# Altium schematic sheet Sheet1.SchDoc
size A3; SheetNumber: 1; SheetTotal: 1
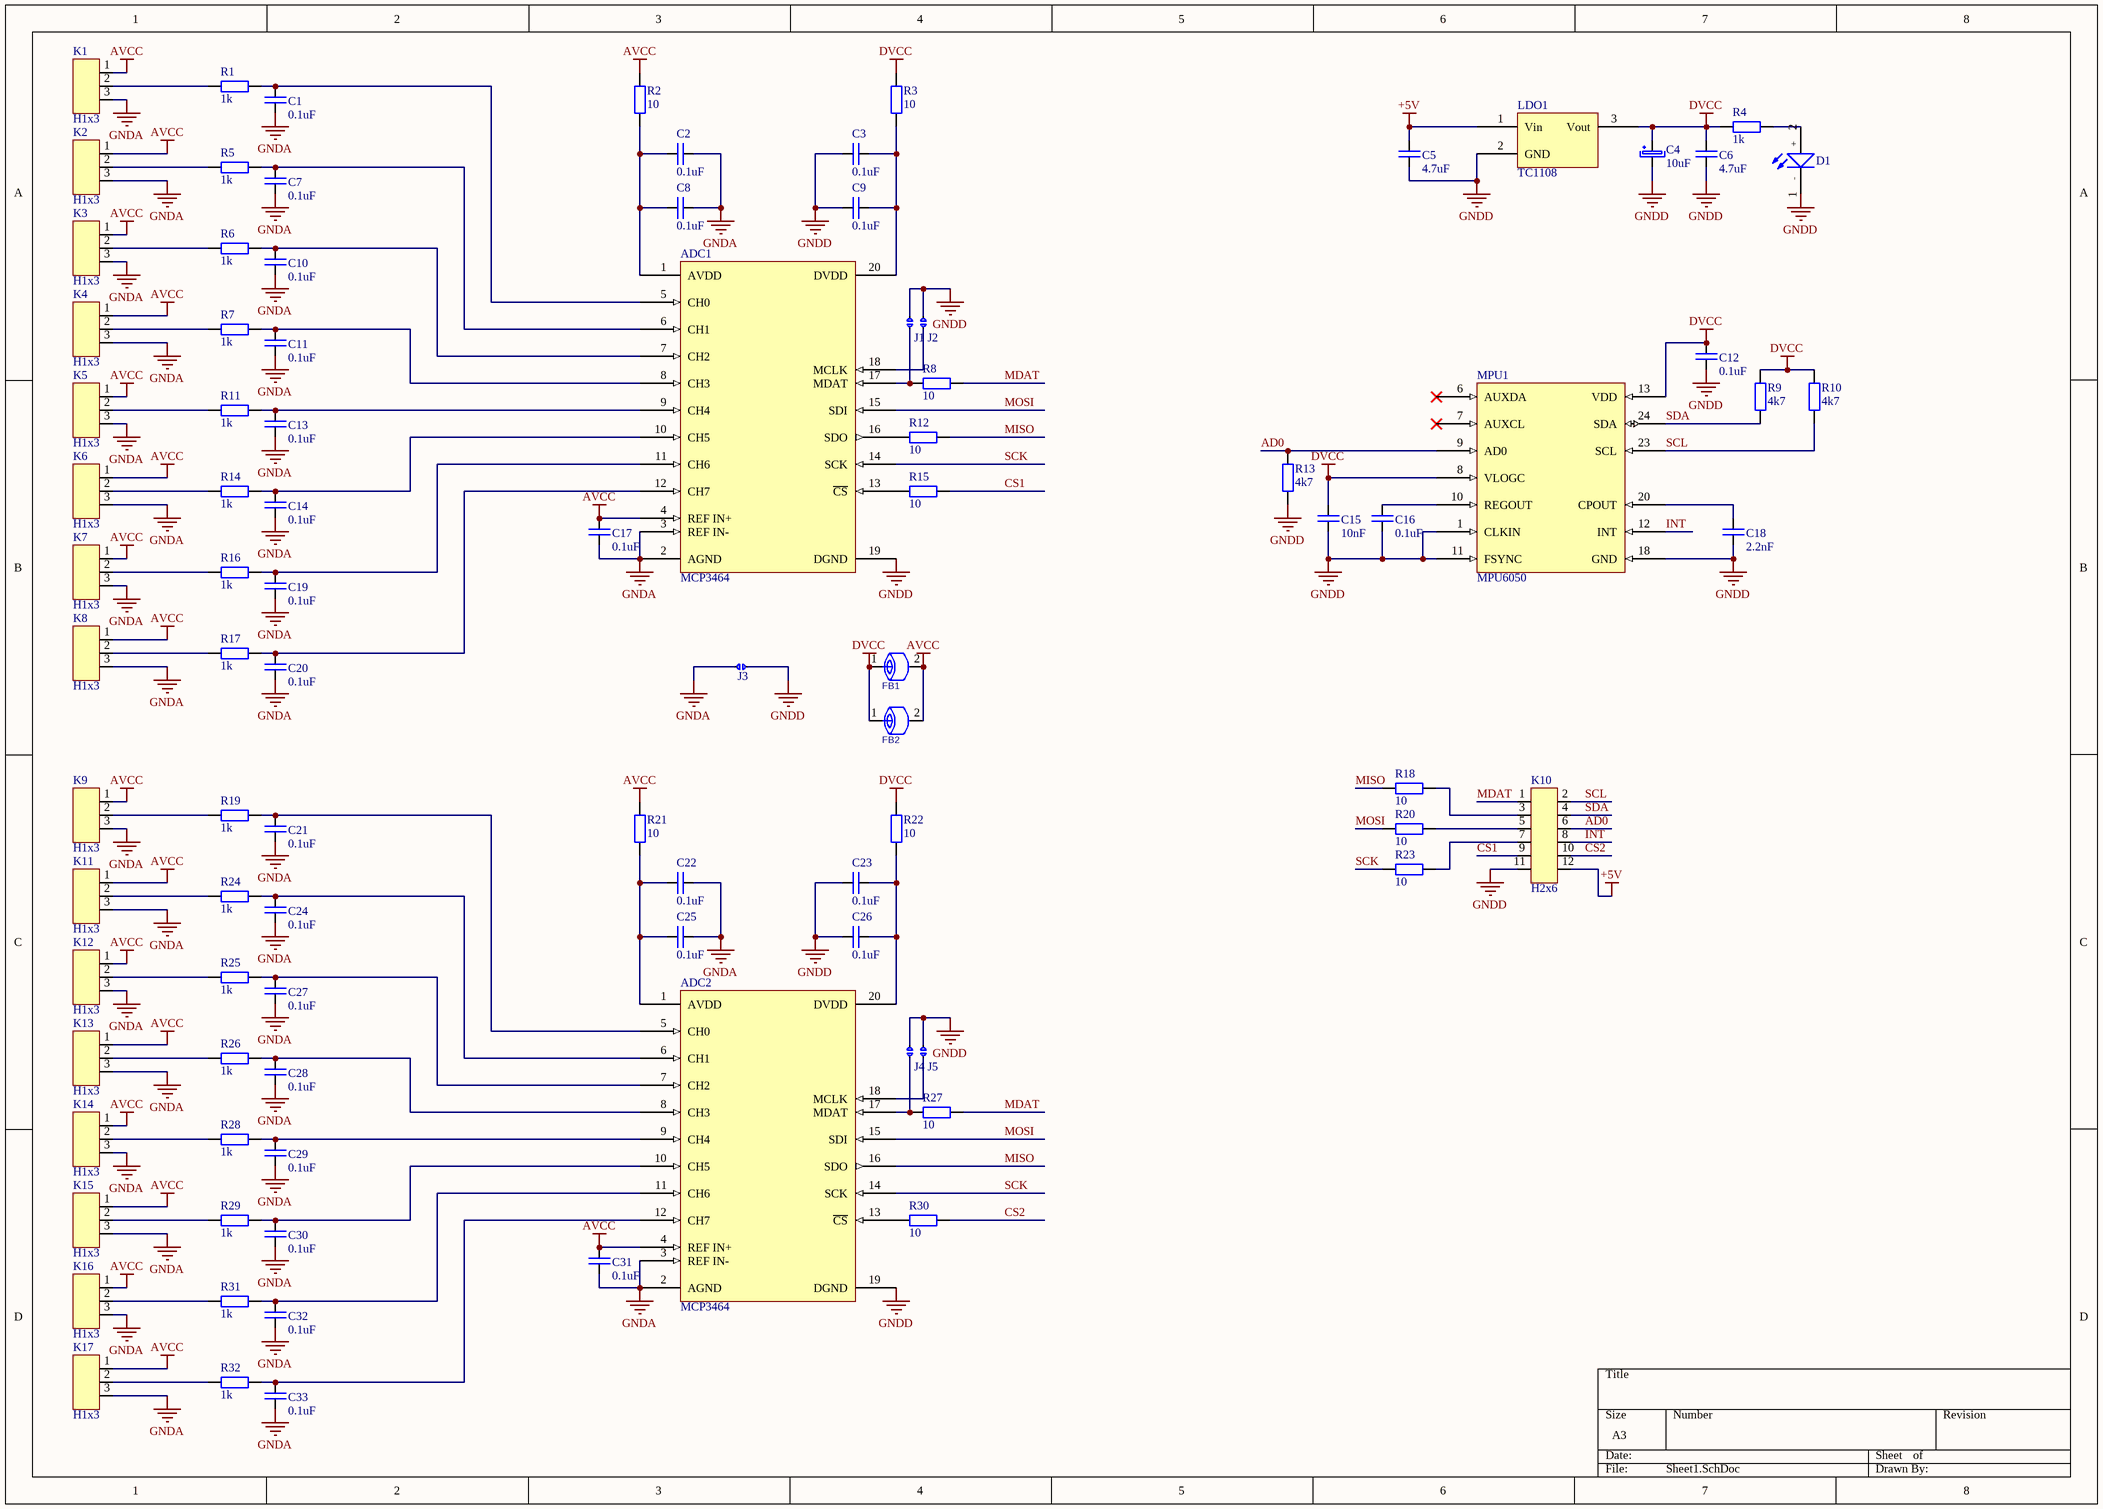
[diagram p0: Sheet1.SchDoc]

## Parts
ADC1  MCP3464  [TSOP65P640X120-20N ADC]
ADC2  MCP3464  [TSOP65P640X120-20N ADC]
C1  0.1uF  [C1608_0603I_M]
C2  0.1uF  [C1608_0603I_M]
C3  0.1uF  [C1608_0603I_M]
C4  10uF  [C Tantal A]
C5  4.7uF  [C1608_0603I_M]
C6  4.7uF  [C1608_0603I_M]
C7  0.1uF  [C1608_0603I_M]
C8  0.1uF  [C1608_0603I_M]
C9  0.1uF  [C1608_0603I_M]
C10  0.1uF  [C1608_0603I_M]
C11  0.1uF  [C1608_0603I_M]
C12  0.1uF  [C1608_0603I_M]
C13  0.1uF  [C1608_0603I_M]
C14  0.1uF  [C1608_0603I_M]
C15  10nF  [C1608_0603I_M]
C16  0.1uF  [C1608_0603I_M]
C17  0.1uF  [C1608_0603I_M]
C18  2.2nF  [C1608_0603I_M]
C19  0.1uF  [C1608_0603I_M]
C20  0.1uF  [C1608_0603I_M]
C21  0.1uF  [C1608_0603I_M]
C22  0.1uF  [C1608_0603I_M]
C23  0.1uF  [C1608_0603I_M]
C24  0.1uF  [C1608_0603I_M]
C25  0.1uF  [C1608_0603I_M]
C26  0.1uF  [C1608_0603I_M]
C27  0.1uF  [C1608_0603I_M]
C28  0.1uF  [C1608_0603I_M]
C29  0.1uF  [C1608_0603I_M]
C30  0.1uF  [C1608_0603I_M]
C31  0.1uF  [C1608_0603I_M]
C32  0.1uF  [C1608_0603I_M]
C33  0.1uF  [C1608_0603I_M]
D1  LED  [LED1608_0603I_M]  (value not drawn)
FB1  FERITTE BEAD  [R1608_0603I_M]  (value not drawn)
FB2  FERITTE BEAD  [R1608_0603I_M]  (value not drawn)
J1  JMP_mini  [solderJumper]  (value not drawn)
J2  JMP_mini  [solderJumper]  (value not drawn)
J3  JMP_mini  [solderJumper]  (value not drawn)
J4  JMP_mini  [solderJumper]  (value not drawn)
J5  JMP_mini  [solderJumper]  (value not drawn)
K1  H1x3  [H1x3]
K2  H1x3  [H1x3]
K3  H1x3  [H1x3]
K4  H1x3  [H1x3]
K5  H1x3  [H1x3]
K6  H1x3  [H1x3]
K7  H1x3  [H1x3]
K8  H1x3  [H1x3]
K9  H1x3  [H1x3]
K10  H2x6  [H2x6]
K11  H1x3  [H1x3]
K12  H1x3  [H1x3]
K13  H1x3  [H1x3]
K14  H1x3  [H1x3]
K15  H1x3  [H1x3]
K16  H1x3  [H1x3]
K17  H1x3  [H1x3]
LDO1  TC1108  [SOT230P700X180-4N 3V3 LDO]
MPU1  MPU6050  [QFN50P400X400X95_HS-25N]
R1  1k  [R1608_0603I_M]
R2  10  [R1608_0603I_M]
R3  10  [R1608_0603I_M]
R4  1k  [R1608_0603I_M]
R5  1k  [R1608_0603I_M]
R6  1k  [R1608_0603I_M]
R7  1k  [R1608_0603I_M]
R8  10  [R1608_0603I_M]
R9  4k7  [R1608_0603I_M]
R10  4k7  [R1608_0603I_M]
R11  1k  [R1608_0603I_M]
R12  10  [R1608_0603I_M]
R13  4k7  [R1608_0603I_M]
R14  1k  [R1608_0603I_M]
R15  10  [R1608_0603I_M]
R16  1k  [R1608_0603I_M]
R17  1k  [R1608_0603I_M]
R18  10  [R1608_0603I_M]
R19  1k  [R1608_0603I_M]
R20  10  [R1608_0603I_M]
R21  10  [R1608_0603I_M]
R22  10  [R1608_0603I_M]
R23  10  [R1608_0603I_M]
R24  1k  [R1608_0603I_M]
R25  1k  [R1608_0603I_M]
R26  1k  [R1608_0603I_M]
R27  10  [R1608_0603I_M]
R28  1k  [R1608_0603I_M]
R29  1k  [R1608_0603I_M]
R30  10  [R1608_0603I_M]
R31  1k  [R1608_0603I_M]
R32  1k  [R1608_0603I_M]

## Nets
+5V: C5.1 K10.12 LDO1.1(Vin)
AVCC: ADC1.4(REF_IN+) ADC2.4(REF_IN+) C17.2 C31.2 FB1.2 FB2.2 K1.1 K2.1 K3.1 K4.1 K5.1 K6.1 K7.1 K8.1 K9.1 K11.1 K12.1 K13.1 K14.1 K15.1 K16.1 K17.1 R2.1 R21.1
DVCC: C4.1 C6.1 C12.2 C15.1 FB1.1 FB2.1 LDO1.3(Vout) MPU1.8(VLOGC) MPU1.13(VDD) R3.1 R4.1 R9.2 R10.1 R22.1
GNDA: ADC1.2(AGND) ADC1.3(REF_IN-) ADC2.2(AGND) ADC2.3(REF_IN-) C1.1 C2.2 C7.1 C8.2 C10.1 C11.1 C13.1 C14.1 C17.1 C19.1 C20.1 C21.1 C22.2 C24.1 C25.2 C27.1 C28.1 C29.1 C30.1 C31.1 C32.1 C33.1 J3.2 K1.3 K2.3 K3.3 K4.3 K5.3 K6.3 K7.3 K8.3 K9.3 K11.3 K12.3 K13.3 K14.3 K15.3 K16.3 K17.3
GNDD: ADC1.19(DGND) ADC2.19(DGND) C3.1 C4.2 C5.2 C6.2 C9.1 C12.1 C15.2 C16.1 C18.2 C23.1 C26.1 D1.1(-) J1.2 J2.2 J3.1 J4.2 J5.2 K10.11 LDO1.2(GND) MPU1.1(CLKIN) MPU1.11(FSYNC) MPU1.18(GND) R13.2
AD0: K10.6 MPU1.9(AD0) R13.1
CS1: K10.9 R15.2
CS2: K10.10 R30.2
INT: K10.8 MPU1.12(INT)
MDAT: K10.1 R8.2 R27.2
MISO: ADC2.16(SDO) R12.2 R18.1
MOSI: ADC1.15(SDI) ADC2.15(SDI) R20.1
SCK: ADC1.14(SCK) ADC2.14(SCK) R23.1
SCL: K10.2 MPU1.23(SCL) R10.2
SDA: K10.4 MPU1.24(SDA) R9.1
NetADC1_1: ADC1.1(AVDD) C2.1 C8.1 R2.2
NetADC1_5: ADC1.5(CH0) C1.2 R1.2
NetADC1_6: ADC1.6(CH1) C7.2 R5.2
NetADC1_7: ADC1.7(CH2) C10.2 R6.2
NetADC1_8: ADC1.8(CH3) C11.2 R7.2
NetADC1_9: ADC1.9(CH4) C13.2 R11.2
NetADC1_10: ADC1.10(CH5) C14.2 R14.2
NetADC1_11: ADC1.11(CH6) C19.2 R16.2
NetADC1_12: ADC1.12(CH7) C20.2 R17.2
NetADC1_13: ADC1.13(~{CS}) R15.1
NetADC1_16: ADC1.16(SDO) R12.1
NetADC1_17: ADC1.17(MDAT) J1.1 R8.1
NetADC1_18: ADC1.18(MCLK) J2.1
NetADC1_20: ADC1.20(DVDD) C3.2 C9.2 R3.2
NetADC2_1: ADC2.1(AVDD) C22.1 C25.1 R21.2
NetADC2_5: ADC2.5(CH0) C21.2 R19.2
NetADC2_6: ADC2.6(CH1) C24.2 R24.2
NetADC2_7: ADC2.7(CH2) C27.2 R25.2
NetADC2_8: ADC2.8(CH3) C28.2 R26.2
NetADC2_9: ADC2.9(CH4) C29.2 R28.2
NetADC2_10: ADC2.10(CH5) C30.2 R29.2
NetADC2_11: ADC2.11(CH6) C32.2 R31.2
NetADC2_12: ADC2.12(CH7) C33.2 R32.2
NetADC2_13: ADC2.13(~{CS}) R30.1
NetADC2_17: ADC2.17(MDAT) J4.1 R27.1
NetADC2_18: ADC2.18(MCLK) J5.1
NetADC2_20: ADC2.20(DVDD) C23.2 C26.2 R22.2
NetC16_2: C16.2 MPU1.10(REGOUT)
NetC18_1: C18.1 MPU1.20(CPOUT)
NetD1_2: D1.2(+) R4.2
NetK1_2: K1.2 R1.1
NetK2_2: K2.2 R5.1
NetK3_2: K3.2 R6.1
NetK4_2: K4.2 R7.1
NetK5_2: K5.2 R11.1
NetK6_2: K6.2 R14.1
NetK7_2: K7.2 R16.1
NetK8_2: K8.2 R17.1
NetK9_2: K9.2 R19.1
NetK10_3: K10.3 R18.2
NetK10_5: K10.5 R20.2
NetK10_7: K10.7 R23.2
NetK11_2: K11.2 R24.1
NetK12_2: K12.2 R25.1
NetK13_2: K13.2 R26.1
NetK14_2: K14.2 R28.1
NetK15_2: K15.2 R29.1
NetK16_2: K16.2 R31.1
NetK17_2: K17.2 R32.1

Not connected (* = marked no-connect by the designer): MPU1 6(AUXDA)* 7(AUXCL)*

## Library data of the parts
C1-C3 C5-C33 = C: Capacitor
C4 = C+: Capacitor Polarized
K1-K9 K11-K17 = H1x3: Header 1x3 (male)
K10 = H2x6: Header 2x5 (male)
R1-R32 = R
